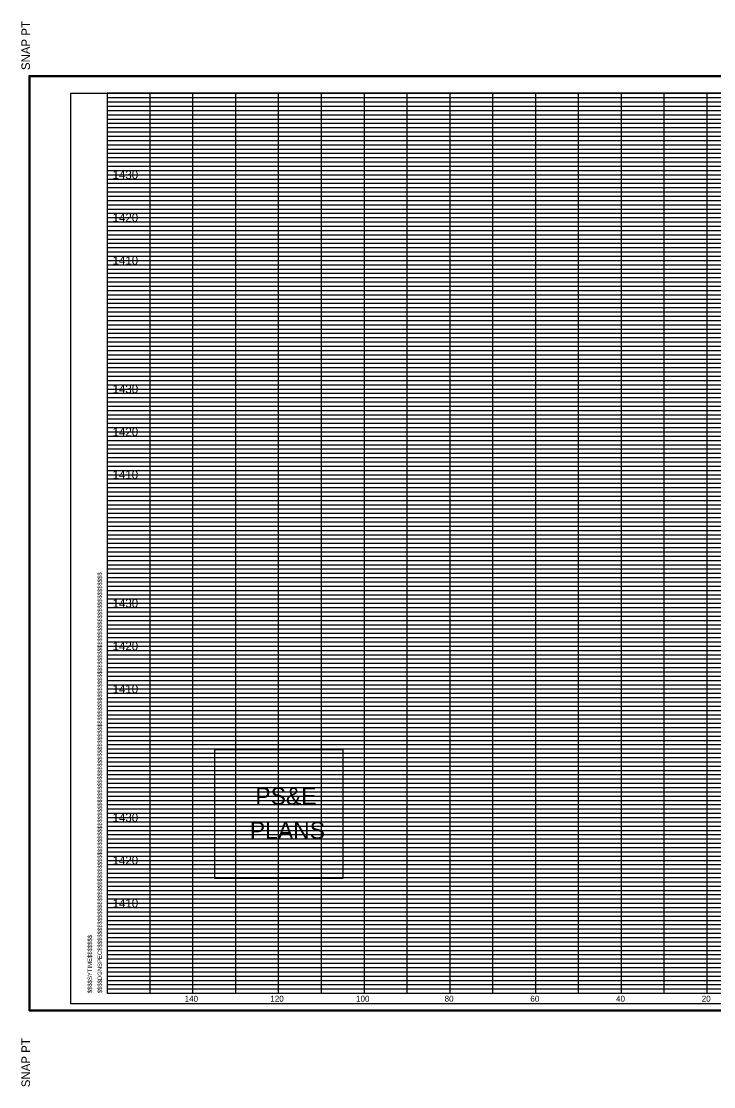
# Model space of a CAD drawing. Extents: x 980 to 1324, y 978 to 1227.
# Drawn here: x 979.9 to 1141.5, y 978.2 to 1226.8 of the extents above; entities that cross this region are included whole.
import ezdxf

# ---------------------------------------------------------------- set-up
doc = ezdxf.new("R2010")
doc.units = 0
for name, color, linetype in [('DESIGN - SHEET - Corner Text', 7, 'Continuous'), ('DESIGN - SHEET - Light Grid', 7, 'Continuous'), ('DESIGN - SHEET - Linework', 7, 'Continuous'), ('DESIGN - SHEET - Plot Shape', 7, 'Continuous')]:
    doc.layers.add(name, color=color, linetype=linetype)

msp = doc.modelspace()

# ---------------------------------------------------------------- linework, layer by layer
at = {"layer": 'DESIGN - SHEET - Corner Text'}
msp.add_lwpolyline([(1025.04, 1056.83), (1025.04, 1026.83), (1055.04, 1026.83), (1055.04, 1056.83)], close=True, dxfattribs=at)
at = {"layer": 'DESIGN - SHEET - Light Grid'}
for p, q in [((1000, 1209), (1080, 1209)), ((1080, 1209), (1160, 1209)), ((1000, 1208), (1080, 1208)), ((1000, 1207), (1080, 1207)), ((1000, 1206), (1080, 1206)), ((1080, 1208), (1160, 1208)), ((1080, 1207), (1160, 1207)), ((1080, 1206), (1160, 1206)), ((1000, 1205), (1080, 1205)), ((1000, 1204), (1080, 1204)), ((1080, 1205), (1160, 1205)), ((1080, 1204), (1160, 1204)), ((1000, 1203), (1080, 1203)), ((1000, 1202), (1080, 1202)), ((1000, 1201), (1080, 1201)), ((1080, 1203), (1160, 1203)), ((1080, 1202), (1160, 1202)), ((1080, 1201), (1160, 1201)), ((1000, 1199), (1080, 1199)), ((1080, 1199), (1160, 1199)), ((1000, 1198), (1080, 1198)), ((1000, 1197), (1080, 1197)), ((1000, 1196), (1080, 1196)), ((1080, 1198), (1160, 1198)), ((1080, 1197), (1160, 1197)), ((1080, 1196), (1160, 1196)), ((1000, 1195), (1080, 1195)), ((1000, 1194), (1080, 1194)), ((1080, 1195), (1160, 1195)), ((1080, 1194), (1160, 1194)), ((1000, 1193), (1080, 1193)), ((1000, 1192), (1080, 1192)), ((1000, 1191), (1080, 1191)), ((1080, 1193), (1160, 1193)), ((1080, 1192), (1160, 1192)), ((1080, 1191), (1160, 1191)), ((1000, 1189), (1080, 1189)), ((1080, 1189), (1160, 1189)), ((1000, 1188), (1080, 1188)), ((1000, 1187), (1080, 1187)), ((1000, 1186), (1080, 1186)), ((1080, 1188), (1160, 1188)), ((1080, 1187), (1160, 1187)), ((1080, 1186), (1160, 1186)), ((1000, 1185), (1080, 1185)), ((1000, 1184), (1080, 1184)), ((1080, 1185), (1160, 1185)), ((1080, 1184), (1160, 1184)), ((1000, 1183), (1080, 1183)), ((1000, 1182), (1080, 1182)), ((1000, 1181), (1080, 1181)), ((1080, 1183), (1160, 1183)), ((1080, 1182), (1160, 1182)), ((1080, 1181), (1160, 1181)), ((1000, 1179), (1080, 1179)), ((1080, 1179), (1160, 1179)), ((1000, 1178), (1080, 1178)), ((1000, 1177), (1080, 1177)), ((1080, 1178), (1160, 1178)), ((1080, 1177), (1160, 1177)), ((1000, 1176), (1080, 1176)), ((1000, 1175), (1080, 1175)), ((1000, 1174), (1080, 1174)), ((1080, 1176), (1160, 1176)), ((1080, 1175), (1160, 1175)), ((1080, 1174), (1160, 1174)), ((1000, 1173), (1080, 1173)), ((1000, 1172), (1080, 1172)), ((1080, 1173), (1160, 1173)), ((1080, 1172), (1160, 1172)), ((1000, 1171), (1080, 1171)), ((1000, 1169), (1080, 1169)), ((1080, 1171), (1160, 1171)), ((1080, 1169), (1160, 1169)), ((1000, 1168), (1080, 1168)), ((1000, 1167), (1080, 1167)), ((1080, 1168), (1160, 1168)), ((1080, 1167), (1160, 1167)), ((1000, 1166), (1080, 1166)), ((1000, 1165), (1080, 1165)), ((1000, 1164), (1080, 1164)), ((1080, 1166), (1160, 1166)), ((1080, 1165), (1160, 1165)), ((1080, 1164), (1160, 1164)), ((1000, 1163), (1080, 1163)), ((1000, 1162), (1080, 1162)), ((1080, 1163), (1160, 1163)), ((1080, 1162), (1160, 1162)), ((1000, 1161), (1080, 1161)), ((1000, 1159), (1080, 1159)), ((1080, 1161), (1160, 1161)), ((1080, 1159), (1160, 1159)), ((1000, 1158), (1080, 1158)), ((1000, 1157), (1080, 1157)), ((1080, 1158), (1160, 1158)), ((1080, 1157), (1160, 1157)), ((1000, 1156), (1080, 1156)), ((1000, 1155), (1080, 1155)), ((1000, 1154), (1080, 1154)), ((1080, 1156), (1160, 1156)), ((1080, 1155), (1160, 1155)), ((1080, 1154), (1160, 1154)), ((1000, 1153), (1080, 1153)), ((1000, 1152), (1080, 1152)), ((1080, 1153), (1160, 1153)), ((1080, 1152), (1160, 1152)), ((1000, 1151), (1080, 1151)), ((1000, 1149), (1080, 1149)), ((1080, 1151), (1160, 1151)), ((1080, 1149), (1160, 1149)), ((1000, 1148), (1080, 1148)), ((1000, 1147), (1080, 1147)), ((1080, 1148), (1160, 1148)), ((1080, 1147), (1160, 1147)), ((1000, 1146), (1080, 1146)), ((1000, 1145), (1080, 1145)), ((1000, 1144), (1080, 1144)), ((1080, 1146), (1160, 1146)), ((1080, 1145), (1160, 1145)), ((1080, 1144), (1160, 1144)), ((1000, 1143), (1080, 1143)), ((1000, 1142), (1080, 1142)), ((1080, 1143), (1160, 1143)), ((1080, 1142), (1160, 1142)), ((1000, 1141), (1080, 1141)), ((1000, 1139), (1080, 1139)), ((1080, 1141), (1160, 1141)), ((1080, 1139), (1160, 1139)), ((1000, 1138), (1080, 1138)), ((1000, 1137), (1080, 1137)), ((1080, 1138), (1160, 1138)), ((1080, 1137), (1160, 1137)), ((1000, 1136), (1080, 1136)), ((1000, 1135), (1080, 1135)), ((1000, 1134), (1080, 1134)), ((1080, 1136), (1160, 1136)), ((1080, 1135), (1160, 1135)), ((1080, 1134), (1160, 1134)), ((1000, 1133), (1080, 1133)), ((1000, 1132), (1080, 1132)), ((1080, 1133), (1160, 1133)), ((1080, 1132), (1160, 1132)), ((1000, 1131), (1080, 1131)), ((1000, 1129), (1080, 1129)), ((1080, 1131), (1160, 1131)), ((1080, 1129), (1160, 1129)), ((1000, 1128), (1080, 1128)), ((1000, 1127), (1080, 1127)), ((1080, 1128), (1160, 1128)), ((1080, 1127), (1160, 1127)), ((1000, 1126), (1080, 1126)), ((1000, 1125), (1080, 1125)), ((1000, 1124), (1080, 1124)), ((1080, 1126), (1160, 1126)), ((1080, 1125), (1160, 1125)), ((1080, 1124), (1160, 1124)), ((1000, 1123), (1080, 1123)), ((1000, 1122), (1080, 1122)), ((1080, 1123), (1160, 1123)), ((1080, 1122), (1160, 1122)), ((1000, 1121), (1080, 1121)), ((1000, 1119), (1080, 1119)), ((1080, 1121), (1160, 1121)), ((1080, 1119), (1160, 1119)), ((1000, 1118), (1080, 1118)), ((1000, 1117), (1080, 1117)), ((1080, 1118), (1160, 1118)), ((1080, 1117), (1160, 1117)), ((1000, 1116), (1080, 1116)), ((1000, 1115), (1080, 1115)), ((1000, 1114), (1080, 1114)), ((1080, 1116), (1160, 1116)), ((1080, 1115), (1160, 1115)), ((1080, 1114), (1160, 1114)), ((1000, 1113), (1080, 1113)), ((1000, 1112), (1080, 1112)), ((1080, 1113), (1160, 1113)), ((1080, 1112), (1160, 1112)), ((1000, 1111), (1080, 1111)), ((1000, 1109), (1080, 1109)), ((1080, 1111), (1160, 1111)), ((1080, 1109), (1160, 1109)), ((1000, 1108), (1080, 1108)), ((1000, 1107), (1080, 1107)), ((1080, 1108), (1160, 1108)), ((1080, 1107), (1160, 1107)), ((1000, 1106), (1080, 1106)), ((1000, 1105), (1080, 1105)), ((1000, 1104), (1080, 1104)), ((1080, 1106), (1160, 1106)), ((1080, 1105), (1160, 1105)), ((1080, 1104), (1160, 1104)), ((1000, 1103), (1080, 1103)), ((1000, 1102), (1080, 1102)), ((1080, 1103), (1160, 1103)), ((1080, 1102), (1160, 1102)), ((1000, 1101), (1080, 1101)), ((1000, 1099), (1080, 1099)), ((1080, 1101), (1160, 1101)), ((1080, 1099), (1160, 1099)), ((1000, 1098), (1080, 1098)), ((1000, 1097), (1080, 1097)), ((1080, 1098), (1160, 1098)), ((1080, 1097), (1160, 1097)), ((1000, 1096), (1080, 1096)), ((1000, 1095), (1080, 1095)), ((1000, 1094), (1080, 1094)), ((1080, 1096), (1160, 1096)), ((1080, 1095), (1160, 1095)), ((1080, 1094), (1160, 1094)), ((1000, 1093), (1080, 1093)), ((1000, 1092), (1080, 1092)), ((1080, 1093), (1160, 1093)), ((1080, 1092), (1160, 1092)), ((1000, 1091), (1080, 1091)), ((1000, 1089), (1080, 1089)), ((1080, 1091), (1160, 1091)), ((1080, 1089), (1160, 1089)), ((1000, 1088), (1080, 1088)), ((1000, 1087), (1080, 1087)), ((1080, 1088), (1160, 1088)), ((1080, 1087), (1160, 1087)), ((1000, 1086), (1080, 1086)), ((1000, 1085), (1080, 1085)), ((1080, 1086), (1160, 1086)), ((1080, 1085), (1160, 1085)), ((1000, 1084), (1080, 1084)), ((1000, 1083), (1080, 1083)), ((1000, 1082), (1080, 1082)), ((1080, 1084), (1160, 1084)), ((1080, 1083), (1160, 1083)), ((1080, 1082), (1160, 1082)), ((1000, 1081), (1080, 1081)), ((1080, 1081), (1160, 1081)), ((1000, 1079), (1080, 1079)), ((1000, 1078), (1080, 1078)), ((1000, 1077), (1080, 1077)), ((1080, 1079), (1160, 1079)), ((1080, 1078), (1160, 1078)), ((1080, 1077), (1160, 1077)), ((1000, 1076), (1080, 1076)), ((1000, 1075), (1080, 1075)), ((1080, 1076), (1160, 1076)), ((1080, 1075), (1160, 1075)), ((1000, 1074), (1080, 1074)), ((1000, 1073), (1080, 1073)), ((1000, 1072), (1080, 1072)), ((1080, 1074), (1160, 1074)), ((1080, 1073), (1160, 1073)), ((1080, 1072), (1160, 1072)), ((1000, 1071), (1080, 1071)), ((1080, 1071), (1160, 1071)), ((1000, 1069), (1080, 1069)), ((1000, 1068), (1080, 1068)), ((1000, 1067), (1080, 1067)), ((1080, 1069), (1160, 1069)), ((1080, 1068), (1160, 1068)), ((1080, 1067), (1160, 1067)), ((1000, 1066), (1080, 1066)), ((1000, 1065), (1080, 1065)), ((1080, 1066), (1160, 1066)), ((1080, 1065), (1160, 1065)), ((1000, 1064), (1080, 1064)), ((1000, 1063), (1080, 1063)), ((1000, 1062), (1080, 1062)), ((1080, 1064), (1160, 1064)), ((1080, 1063), (1160, 1063)), ((1080, 1062), (1160, 1062)), ((1000, 1061), (1080, 1061)), ((1080, 1061), (1160, 1061)), ((1000, 1059), (1080, 1059)), ((1000, 1058), (1080, 1058)), ((1000, 1057), (1080, 1057)), ((1080, 1059), (1160, 1059)), ((1080, 1058), (1160, 1058)), ((1080, 1057), (1160, 1057)), ((1000, 1056), (1080, 1056)), ((1000, 1055), (1080, 1055)), ((1080, 1056), (1160, 1056)), ((1080, 1055), (1160, 1055)), ((1000, 1054), (1080, 1054)), ((1000, 1053), (1080, 1053)), ((1000, 1052), (1080, 1052)), ((1080, 1054), (1160, 1054)), ((1080, 1053), (1160, 1053)), ((1080, 1052), (1160, 1052)), ((1000, 1051), (1080, 1051)), ((1080, 1051), (1160, 1051)), ((1000, 1049), (1080, 1049)), ((1000, 1048), (1080, 1048)), ((1000, 1047), (1080, 1047)), ((1080, 1049), (1160, 1049)), ((1080, 1048), (1160, 1048)), ((1080, 1047), (1160, 1047)), ((1000, 1046), (1080, 1046)), ((1000, 1045), (1080, 1045)), ((1080, 1046), (1160, 1046)), ((1080, 1045), (1160, 1045)), ((1000, 1044), (1080, 1044)), ((1000, 1043), (1080, 1043)), ((1000, 1042), (1080, 1042)), ((1080, 1044), (1160, 1044)), ((1080, 1043), (1160, 1043)), ((1080, 1042), (1160, 1042)), ((1000, 1041), (1080, 1041)), ((1080, 1041), (1160, 1041)), ((1000, 1039), (1080, 1039)), ((1000, 1038), (1080, 1038)), ((1000, 1037), (1080, 1037)), ((1080, 1039), (1160, 1039)), ((1080, 1038), (1160, 1038)), ((1080, 1037), (1160, 1037)), ((1000, 1036), (1080, 1036)), ((1000, 1035), (1080, 1035)), ((1080, 1036), (1160, 1036)), ((1080, 1035), (1160, 1035)), ((1000, 1034), (1080, 1034)), ((1000, 1033), (1080, 1033)), ((1000, 1032), (1080, 1032)), ((1080, 1034), (1160, 1034)), ((1080, 1033), (1160, 1033)), ((1080, 1032), (1160, 1032)), ((1000, 1031), (1080, 1031)), ((1080, 1031), (1160, 1031)), ((1000, 1029), (1080, 1029)), ((1000, 1028), (1080, 1028)), ((1000, 1027), (1080, 1027)), ((1080, 1029), (1160, 1029)), ((1080, 1028), (1160, 1028)), ((1080, 1027), (1160, 1027)), ((1000, 1026), (1080, 1026)), ((1000, 1025), (1080, 1025)), ((1080, 1026), (1160, 1026)), ((1080, 1025), (1160, 1025)), ((1000, 1024), (1080, 1024)), ((1000, 1023), (1080, 1023)), ((1000, 1022), (1080, 1022)), ((1080, 1024), (1160, 1024)), ((1080, 1023), (1160, 1023)), ((1080, 1022), (1160, 1022)), ((1000, 1021), (1080, 1021)), ((1080, 1021), (1160, 1021)), ((1000, 1019), (1080, 1019)), ((1000, 1018), (1080, 1018)), ((1000, 1017), (1080, 1017)), ((1080, 1019), (1160, 1019)), ((1080, 1018), (1160, 1018)), ((1080, 1017), (1160, 1017)), ((1000, 1016), (1080, 1016)), ((1000, 1015), (1080, 1015)), ((1080, 1016), (1160, 1016)), ((1080, 1015), (1160, 1015)), ((1000, 1014), (1080, 1014)), ((1000, 1013), (1080, 1013)), ((1000, 1012), (1080, 1012)), ((1080, 1014), (1160, 1014)), ((1080, 1013), (1160, 1013)), ((1080, 1012), (1160, 1012)), ((1000, 1011), (1080, 1011)), ((1080, 1011), (1160, 1011)), ((1000, 1009), (1080, 1009)), ((1000, 1008), (1080, 1008)), ((1000, 1007), (1080, 1007)), ((1080, 1009), (1160, 1009)), ((1080, 1008), (1160, 1008)), ((1080, 1007), (1160, 1007)), ((1000, 1006), (1080, 1006)), ((1000, 1005), (1080, 1005)), ((1080, 1006), (1160, 1006)), ((1080, 1005), (1160, 1005)), ((1000, 1004), (1080, 1004)), ((1000, 1003), (1080, 1003)), ((1000, 1002), (1080, 1002)), ((1080, 1004), (1160, 1004)), ((1080, 1003), (1160, 1003)), ((1080, 1002), (1160, 1002)), ((1000, 1001), (1080, 1001)), ((1080, 1001), (1160, 1001))]:
    msp.add_line(p, q, dxfattribs=at)
at = {"layer": 'DESIGN - SHEET - Linework'}
for p, q in [((981.77, 995.86), (981.77, 1214.14)), ((981.77, 1214.14), (1322.17, 1214.14)), ((1010, 1000), (1010, 1210)), ((1020, 1000), (1020, 1210)), ((1030, 1000), (1030, 1210)), ((1040, 1000), (1040, 1210)), ((1050, 1000), (1050, 1210)), ((1060, 1000), (1060, 1210)), ((1070, 1000), (1070, 1210)), ((1080, 1000), (1080, 1210)), ((1090, 1000), (1090, 1210)), ((1100, 1000), (1100, 1210)), ((1110, 1000), (1110, 1210)), ((1120, 1000), (1120, 1210)), ((1130, 1000), (1130, 1210)), ((1140, 1000), (1140, 1210)), ((1000, 1200), (1280, 1200)), ((1000, 1190), (1320, 1190)), ((1000, 1180), (1320, 1180)), ((1000, 1170), (1320, 1170)), ((1000, 1160), (1320, 1160)), ((1000, 1150), (1320, 1150)), ((1000, 1140), (1320, 1140)), ((1000, 1130), (1320, 1130)), ((1000, 1120), (1320, 1120)), ((1000, 1110), (1320, 1110)), ((1000, 1100), (1320, 1100)), ((1000, 1090), (1320, 1090)), ((1000, 1080), (1320, 1080)), ((1000, 1070), (1320, 1070)), ((1000, 1060), (1320, 1060)), ((1000, 1050), (1320, 1050)), ((1000, 1040), (1320, 1040)), ((1000, 1030), (1320, 1030)), ((1000, 1020), (1320, 1020)), ((1000, 1010), (1320, 1010)), ((981.77, 995.86), (1322.17, 995.86))]:
    msp.add_line(p, q, dxfattribs=at)
msp.add_lwpolyline([(1000, 1210), (1000, 1000), (1320, 1000), (1320, 1210), (1000, 1210)], dxfattribs=at)
at = {"layer": 'DESIGN - SHEET - Plot Shape'}
for points in [[(981.97, 1213.94), (1321.97, 1213.94), (1321.97, 996.06), (981.97, 996.06)], [(991.5, 1210), (1320, 1210), (1320, 997.5), (991.5, 997.5)]]:
    msp.add_lwpolyline(points, close=True, dxfattribs=at)

# ---------------------------------------------------------------- texts
at = {"layer": 'DESIGN - SHEET - Corner Text'}
for s, height, p in [('  SNAP PT', 2, (981.97, 1213.94)), ('$$$$DGNSPEC$$$$$$$$$$$$$$$$$$$$$$$$$$$$$$$$$$$$$$$$$$$$$$$$$$$$$$$$$$$$$$$$$$$$$$$$$$$$$$$$$$$$$$$$$$$$$$$$$$$$$$$$$$$$$$$$$$$', 1.00002, (998.74, 1000)), ('$$$$SYTIME$$$$$$$', 1, (996.42, 1000)), ('SNAP PT  ', 2, (981.97, 978.06))]:
    msp.add_text(s, height=height, rotation=90, dxfattribs=at).set_placement(p)
for s, height, p in [('1430', 2, (1001.25, 1190)), ('1420', 2, (1001.25, 1180)), ('1410', 2, (1001.25, 1170)), ('1430', 2, (1001.25, 1140)), ('1420', 2, (1001.25, 1130)), ('1410', 2, (1001.25, 1120)), ('1430', 2, (1001.25, 1090)), ('1420', 2, (1001.25, 1080)), ('1410', 2, (1001.25, 1070)), ('PS&E', 4, (1034.56, 1044.01)), ('1430', 2, (1001.25, 1040)), ('PLANS', 4, (1033.27, 1036.01)), ('1420', 2, (1001.25, 1030)), ('1410', 2, (1001.25, 1020)), ('140', 1.4, (1018.06, 998)), ('120', 1.4, (1038.06, 998)), ('100', 1.4, (1058.06, 998)), ('80', 1.4, (1078.74, 998)), ('60', 1.4, (1098.74, 998)), ('40', 1.4, (1118.74, 998)), ('20', 1.4, (1138.74, 998))]:
    msp.add_text(s, height=height, dxfattribs=at).set_placement(p)

doc.saveas('drawing.dxf')
